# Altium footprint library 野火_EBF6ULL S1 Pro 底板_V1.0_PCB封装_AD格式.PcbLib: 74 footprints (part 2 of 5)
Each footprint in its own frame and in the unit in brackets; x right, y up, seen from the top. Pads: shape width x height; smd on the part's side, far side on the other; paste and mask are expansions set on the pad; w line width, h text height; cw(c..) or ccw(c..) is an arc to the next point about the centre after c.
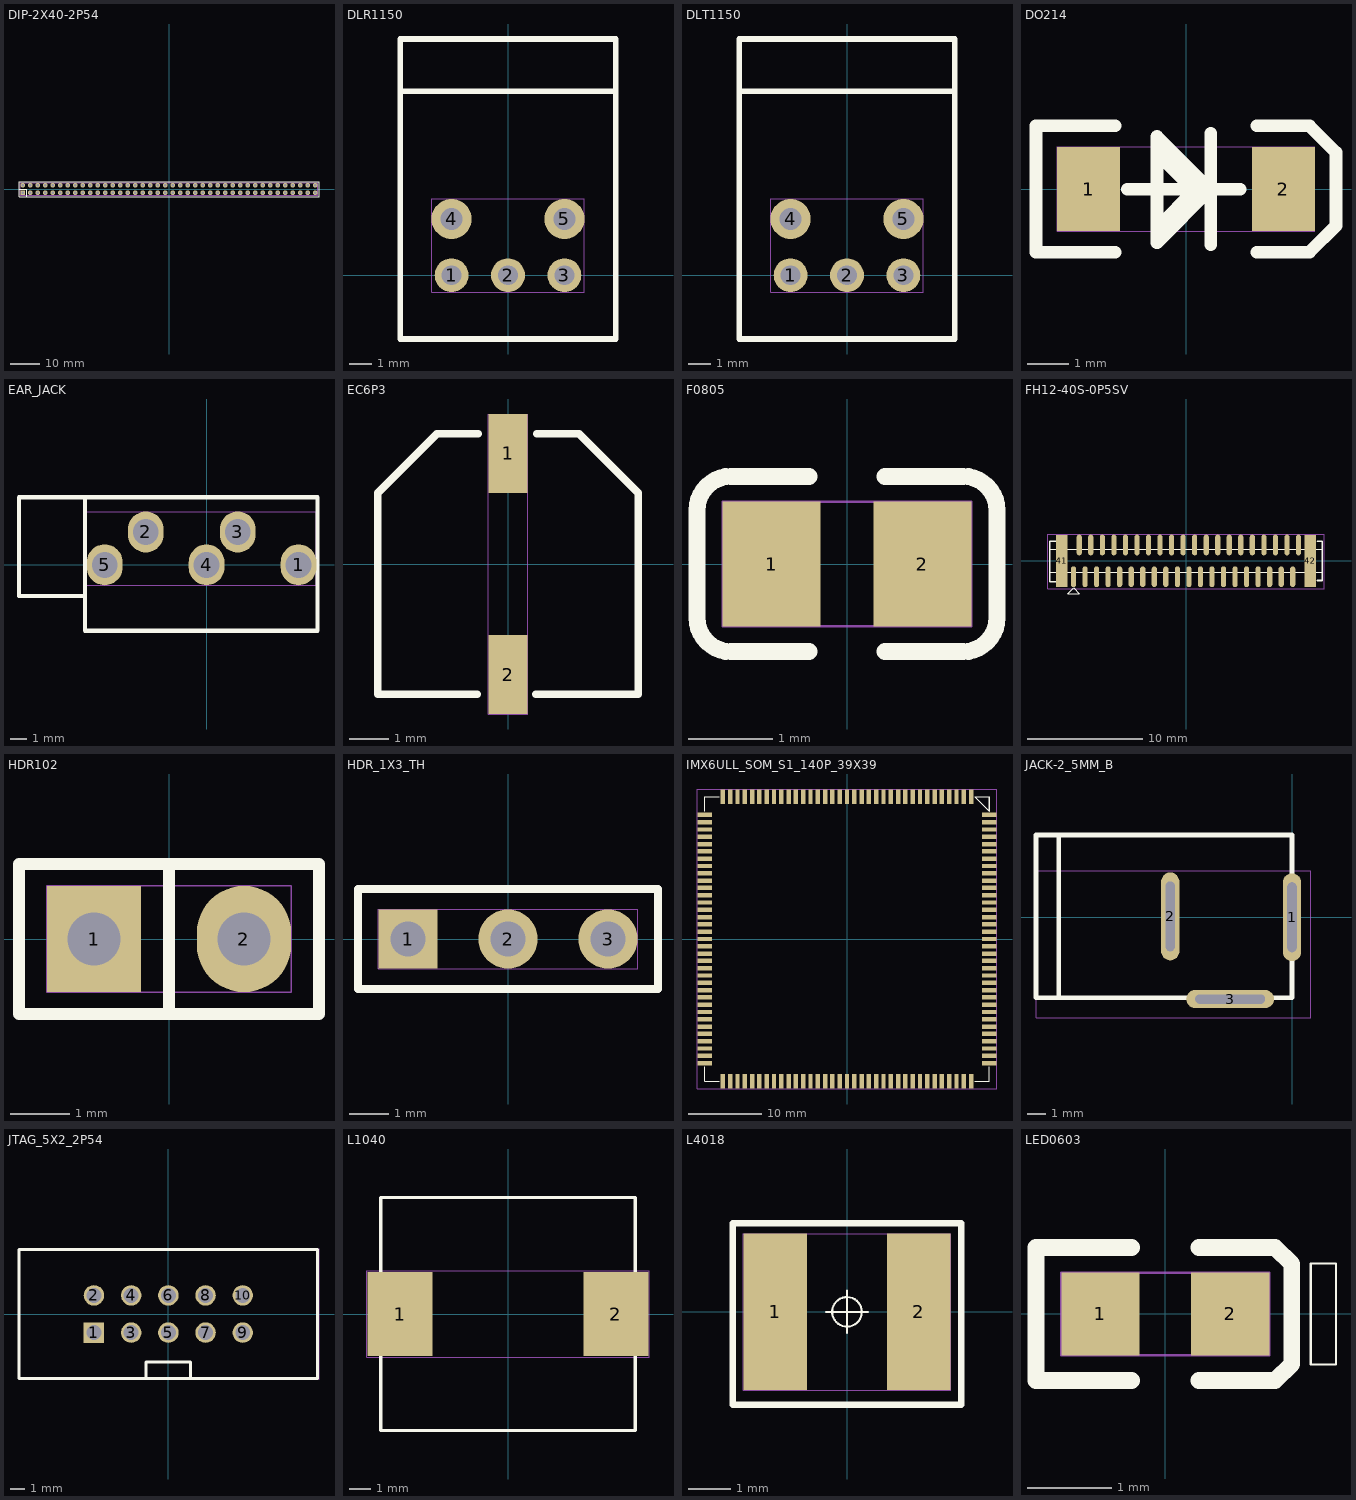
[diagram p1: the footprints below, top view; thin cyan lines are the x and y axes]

## DIP-2X40-2P54 [mil]
pads (80):
  rect 62.99x62.99 hole 35.43 mask+2: 1(-1950,-50)
  round 62.99 hole 35.43 mask+2: 2(-1950,50) 3(-1850,-50) 4(-1850,50) 5(-1750,-50) 6(-1750,50) 7(-1650,-50) 8(-1650,50) 9(-1550,-50) 10(-1550,50) 11(-1450,-50) 12(-1450,50) 13(-1350,-50) 14(-1350,50) 15(-1250,-50) 16(-1250,50) 17(-1150,-50) 18(-1150,50) 19(-1050,-50) 20(-1050,50) 21(-950,-50) 22(-950,50) 23(-850,-50) 24(-850,50) 25(-750,-50) 26(-750,50) 27(-650,-50) 28(-650,50) 29(-550,-50) 30(-550,50) 31(-450,-50) 32(-450,50) 33(-350,-50) 34(-350,50) 35(-250,-50) 36(-250,50) 37(-150,-50) 38(-150,50) 39(-50,-50) 40(-50,50) 41(50,-50) 42(50,50) 43(150,-50) 44(150,50) 45(250,-50) 46(250,50) 47(350,-50) 48(350,50) 49(450,-50) 50(450,50) 51(550,-50) 52(550,50) 53(650,-50) 54(650,50) 55(750,-50) 56(750,50) 57(850,-50) 58(850,50) 59(950,-50) 60(950,50) 61(1050,-50) 62(1050,50) 63(1150,-50) 64(1150,50) 65(1250,-50) 66(1250,50) 67(1350,-50) 68(1350,50) 69(1450,-50) 70(1450,50) 71(1550,-50) 72(1550,50) 73(1650,-50) 74(1650,50) 75(1750,-50) 76(1750,50) 77(1850,-50) 78(1850,50) 79(1950,-50) 80(1950,50)
Top Overlay:
  lines w12: -2000,0 -1900,0 -1900,-100 ; -2000,-100 2000,-100 2000,100 -2000,100 -2000,-100
Top Assembly:
  text "CN5" at 65.11,25 h50
Mechanical 20:
  lines w1: -1981,-81 -1981,81 1981,81 1981,-81 -1981,-81

## DLR1150 [mil]
pads (5):
  round 60 hole 35 mask+2: 1(-100,0) 2(0,0) 3(100,0)
  round 70.87 hole 39.37 mask+2: 4(-100,99.61) 5(100,99.61)
Top Overlay:
  lines w10: -190.94,325.98 190.94,325.98 ; -190.94,325.98 -190.94,-112.99 190.94,-112.99 190.94,325.98 ; -190.94,325.98 -190.94,418.5 190.94,418.5 190.94,325.98
Top Assembly:
  text "CN8" at -65.11,-25 h50
Mechanical 20:
  lines w1: -135.43,-30 135.43,-30 135.43,135.04 -135.43,135.04 -135.43,-30

## DLT1150 [mil]
pads (5):
  round 60 hole 35 mask+2: 1(-100,0) 2(0,0) 3(100,0)
  round 70.87 hole 39.37 mask+2: 4(-100,99.61) 5(100,99.61)
Top Overlay:
  lines w10: -190.94,325.98 -190.94,418.5 190.94,418.5 190.94,325.98 ; -190.94,325.98 -190.94,-112.99 190.94,-112.99 190.94,325.98 ; -190.94,325.98 190.94,325.98
Top Assembly:
  text "CN12" at -83.44,-25 h50
Mechanical 20:
  lines w1: -135.43,-30 135.43,-30 135.43,135.04 -135.43,135.04 -135.43,-30

## DO214 [mil]
pads (2):
  rect 60x80 smd mask+2: 1(-92.5,0) 2(92.5,0)
Top Overlay:
  lines w1: -27.58,-25.06 -27.58,22.87 -1.5,22.87 -1.5,-25.06 -27.58,-25.06
  lines w12: -67.5,-60 -142.5,-60 -142.5,60 -67.5,60 ; -55.58,-0.13 51.42,-0.13 ; -27.58,33.87 7.79,-1.51 -25.84,-35.13 ; 23.42,-53.13 23.42,52.87 ; 67.5,-60 117.42,-60 142.5,-34.92 142.5,34.87 117.37,60 67.5,60 ; -27.58,-51.13 23.42,-0.13 23.42,-1.13 -27.58,49.87 -27.58,-51.13
Top Assembly:
  text "D2" at 38.93,25 h50
Mechanical 20:
  lines w1: -122.5,-40 122.5,-40 122.5,40 -122.5,40 -122.5,-40

## EAR_JACK [mil]
pads (5):
  oval 86x98 hole 62 mask+2: 1(220.47,0) 2(-145.67,78.74) 3(74.8,78.74) 4(0,0) 5(-244.1,0)
Top Overlay:
  lines w10: -294.49,-75.03 -449.49,-75.03 -449.49,161.97 -294.49,161.97 ; -291.49,-158.03 -291.49,161.97 265.51,161.97 265.51,-158.03 -291.49,-158.03
Top Assembly:
  text "J32" at 57.25,25 h50
Mechanical 20:
  lines w1: -287.1,-49 263.47,-49 263.47,127.74 -287.1,127.74 -287.1,-49

## EC6P3 [mm]
pads (2):
  rect 1x2 smd mask+0.051: 1(0,2.8) 2(0,-2.8)
Top Overlay:
  lines w0.2: -0.787,-3.3 -3.3,-3.3 -3.3,1.8 -1.8,3.3 -0.762,3.3 ; 0.711,-3.3 3.3,-3.3 3.3,1.8 1.8,3.3 0.737,3.3
Top Assembly:
  text "C93" at -1.621,-0.635 h1.27
Mechanical 20:
  lines w0.025: -0.5,-3.8 0.5,-3.8 0.5,3.8 -0.5,3.8 -0.5,-3.8

## F0805 [mm]
pads (2):
  rect 1.16x1.47 smd mask+0.051: 1(-0.89,0) 2(0.89,0)
Top Overlay:
  lines w0.2: -0.45,-1.035 -1.37,-1.035 cw(c-1.37,-0.635) -1.77,-0.635 -1.77,0.635 cw(c-1.37,0.635) -1.37,1.035 -0.45,1.035 ; 0.45,-1.035 1.37,-1.035 ccw(c1.37,-0.635) 1.77,-0.635 1.77,0.635 ccw(c1.37,0.635) 1.37,1.035 0.45,1.035
Top Assembly:
  text "F1" at -0.617,-0.635 h1.27
Mechanical 20:
  lines w0.025: -1.47,-0.735 1.47,-0.735 1.47,0.735 -1.47,0.735 -1.47,-0.735

## FH12-40S-0P5SV [mil]
height 196
pads (42):
  oval 17.72x70.87 smd mask+1.97: 1(-383.85,-54.13) 2(-364.17,54.13) 3(-344.48,-54.13) 4(-324.8,54.13) 5(-305.11,-54.13) 6(-285.43,54.13) 7(-265.74,-54.13) 8(-246.06,54.13) 9(-226.37,-54.13) 10(-206.69,54.13) 11(-187,-54.13) 12(-167.32,54.13) 13(-147.63,-54.13) 14(-127.96,54.13) 15(-108.26,-54.13) 16(-88.59,54.13) 17(-68.89,-54.13) 18(-49.22,54.13) 19(-29.52,-54.13) 20(-9.85,54.13) 21(9.85,-54.13) 22(29.52,54.13) 23(49.22,-54.13) 24(68.89,54.13) 25(88.59,-54.13) 26(108.26,54.13) 27(127.96,-54.13) 28(147.63,54.13) 29(167.33,-54.13) 30(187,54.13) 31(206.7,-54.13) 32(226.37,54.13) 33(246.07,-54.13) 34(265.74,54.13) 35(285.44,-54.13) 36(305.11,54.13) 37(324.81,-54.13) 38(344.48,54.13) 39(364.17,-54.13) 40(383.85,54.13)
  rect 39.37x177.17 smd mask+1.97: 41(-423.24,0) 42(423.24,0)
Top Overlay:
  lines w1: -464.56,-39.37 -464.56,39.37 464.56,39.37 464.56,-39.37 -464.56,-39.37 ; -403.7,-111.81 -383.7,-91.81 -363.7,-111.81 -403.7,-111.81
  lines w6: -444.89,-70.87 -464.56,-70.87 -464.56,66.93 -444.89,66.93 ; 448.81,-66.93 464.56,-66.93 464.56,66.93 448.81,66.93
Top Assembly:
  text "J16" at 52.14,25 h50
Mechanical 20:
  lines w1: -472.44,-94.49 -472.44,90.55 472.44,90.55 472.44,-94.49 -472.44,-94.49

## HDR102 [mil]
pads (2):
  rect 62.99x70.87 / inner oval 62.99x70.87 / far side rect 62.99x70.87 hole 35.43 mask+1.97: 1(-50,0)
  oval 62.99x70.87 hole 35.43 mask+1.97: 2(50,0)
Top Overlay:
  lines w8: 0,-50 0,50 ; -100,-50 100,-50 100,50 -100,50 -100,-50
Top Assembly:
  text "J30" at -57.25,-25 h50
Mechanical 20:
  lines w1: -81.5,-35.43 81.5,-35.43 81.5,35.43 -81.5,35.43 -81.5,-35.43

## HDR_1X3_TH [mil]
height 47
pads (3):
  rect 59.06x59.06 hole 35.43 mask+2: 1(-100,0)
  round 59.06 hole 35.43 mask+2: 2(0,0) 3(100,0)
Top Overlay:
  lines w7.87: -150,-50 150,-50 150,50 -150,50 -150,-50
Top Assembly:
  text "J37" at -57.25,-25 h50
Mechanical 20:
  lines w1: -129.53,-29.53 129.53,-29.53 129.53,29.53 -129.53,29.53 -129.53,-29.53

## IMX6ULL_SOM_S1_140P_39X39 [mm]
pads (140):
  rect 0.6x2 smd mask+0.05: 1(17,19.5) 2(16,19.5) 3(15,19.5) 4(14,19.5) 5(13,19.5) 6(12,19.5) 7(11,19.5) 8(10,19.5) 9(9,19.5) 10(8,19.5) 11(7,19.5) 12(6,19.5) 13(5,19.5) 14(4,19.5) 15(3,19.5) 16(2,19.5) 17(1,19.5) 18(0,19.5) 19(-1,19.5) 20(-2,19.5) 21(-3,19.5) 22(-4,19.5) 23(-5,19.5) 24(-6,19.5) 25(-7,19.5) 26(-8,19.5) 27(-9,19.5) 28(-10,19.5) 29(-11,19.5) 30(-12,19.5) 31(-13,19.5) 32(-14,19.5) 33(-15,19.5) 34(-16,19.5) 35(-17,19.5) 71(-17,-19.5) 72(-16,-19.5) 73(-15,-19.5) 74(-14,-19.5) 75(-13,-19.5) 76(-12,-19.5) 77(-11,-19.5) 78(-10,-19.5) 79(-9,-19.5) 80(-8,-19.5) 81(-7,-19.5) 82(-6,-19.5) 83(-5,-19.5) 84(-4,-19.5) 85(-3,-19.5) 86(-2,-19.5) 87(-1,-19.5) 88(0,-19.5) 89(1,-19.5) 90(2,-19.5) 91(3,-19.5) 92(4,-19.5) 93(5,-19.5) 94(6,-19.5) 95(7,-19.5) 96(8,-19.5) 97(9,-19.5) 98(10,-19.5) 99(11,-19.5) 100(12,-19.5) 101(13,-19.5) 102(14,-19.5) 103(15,-19.5) 104(16,-19.5) 105(17,-19.5)
  rect 2x0.6 smd mask+0.05: 36(-19.5,17) 37(-19.5,16) 38(-19.5,15) 39(-19.5,14) 40(-19.5,13) 41(-19.5,12) 42(-19.5,11) 43(-19.5,10) 44(-19.5,9) 45(-19.5,8) 46(-19.5,7) 47(-19.5,6) 48(-19.5,5) 49(-19.5,4) 50(-19.5,3) 51(-19.5,2) 52(-19.5,1) 53(-19.5,0) 54(-19.5,-1) 55(-19.5,-2) 56(-19.5,-3) 57(-19.5,-4) 58(-19.5,-5) 59(-19.5,-6) 60(-19.5,-7) 61(-19.5,-8) 62(-19.5,-9) 63(-19.5,-10) 64(-19.5,-11) 65(-19.5,-12) 66(-19.5,-13) 67(-19.5,-14) 68(-19.5,-15) 69(-19.5,-16) 70(-19.5,-17) 106(19.5,-17) 107(19.5,-16) 108(19.5,-15) 109(19.5,-14) 110(19.5,-13) 111(19.5,-12) 112(19.5,-11) 113(19.5,-10) 114(19.5,-9) 115(19.5,-8) 116(19.5,-7) 117(19.5,-6) 118(19.5,-5) 119(19.5,-4) 120(19.5,-3) 121(19.5,-2) 122(19.5,-1) 123(19.5,0) 124(19.5,1) 125(19.5,2) 126(19.5,3) 127(19.5,4) 128(19.5,5) 129(19.5,6) 130(19.5,7) 131(19.5,8) 132(19.5,9) 133(19.5,10) 134(19.5,11) 135(19.5,12) 136(19.5,13) 137(19.5,14) 138(19.5,15) 139(19.5,16) 140(19.5,17)
Top Overlay:
  lines w0.025: 17.495,19.499 19.5,19.5 19.501,17.495 17.495,19.499
  lines w0.152: -19.5,-19.5 -17.5,-19.5 -19.5,-19.5 ; -19.5,-19.5 -19.5,-17.5 -19.5,-19.5 ; -19.5,19.5 -19.5,17.5 -19.5,19.5 ; -19.5,19.5 -17.5,19.5 -19.5,19.5 ; 19.5,-19.5 17.5,-19.5 19.5,-19.5 ; 19.5,-19.5 19.5,-17.5 19.5,-19.5 ; 19.5,19.5 19.5,17.5 19.5,19.5 ; 19.5,19.5 17.5,19.5 19.5,19.5
Top Assembly:
  text "J12" at -1.355,-0.635 h1.27
Mechanical 20:
  lines w0.025: -20.55,-20.55 20.55,-20.55 20.55,20.55 -20.55,20.55 -20.55,-20.55

## JACK-2_5MM_B [mm]
pads (3):
  oval 1x4.81 / inner oval 1x4.81 / far side oval 2x4.81 hole 0.5 slot 3.81 at 90 deg mask+0.05: 1(0,0) 2(-6.659,0.046)
  oval 4.81x1 / inner oval 4.81x1 / far side oval 4.81x2 hole 0.5 slot 3.81 at 0 deg mask+0.05: 3(-3.383,-4.475)
Top Overlay:
  lines w0.254: -12.755,-4.348 -12.755,4.501 ; -14,-4.399 -14,4.501 0,4.501 0,-4.399 -14,-4.399
Top Assembly:
  text "JACK1" at -2.446,-0.635 h1.27
Mechanical 20:
  lines w0.025: -14,-5.491 1.016,-5.491 1.016,2.535 -14,2.535 -14,-5.491

## JTAG_5X2_2P54 [mil]
pads (10):
  rect 55x55 / inner round 55 / far side rect 55x55 hole 40 mask+2.5: 1(-200,-50)
  round 55 hole 40 mask+2.5: 2(-200,50) 3(-100,-50) 4(-100,50) 5(0,-50) 6(0,50) 7(100,-50) 8(100,50) 9(200,-50) 10(200,50)
Top Overlay:
  lines w8: -60,-170 -60,-130 ; -60,-129.37 60,-129.37 ; 60,-170 60,-130 ; -401.57,-173 401.57,-173 401.57,173 -401.57,173 -401.57,-173
Top Assembly:
  text "J1" at -24.29,-25 h50
Mechanical 20:
  lines w1: -400,-175 405,-175 405,175 -400,175 -400,-175

## L1040 [mm]
height 5.283
pads (2):
  rect 3x3.9 smd mask+0.05: 1(-5,0) 2(5,0)
Top Overlay:
  lines w0.152: -5.9,-5.4 5.9,-5.4 5.9,5.4 -5.9,5.4 -5.9,-5.4
Top Assembly:
  text "L1" at 0.584,0.635 h1.27
Mechanical 20:
  lines w0.025: -6.55,-2 6.55,-2 6.55,2 -6.55,2 -6.55,-2

## L4018 [mm]
height 5.283
pads (2):
  rect 1.5x3.7 smd mask+0.05: 1(-1.7,0) 2(1.7,0)
Top Overlay:
  circle w0.05: c0,0 r0.35
  lines w0.05: -0.5,0 0.5,0 ; 0,-0.5 0,0.5
  lines w0.152: -2.7,-2.2 2.7,-2.2 2.7,2.1 -2.7,2.1 -2.7,-2.2
Top Assembly:
  text "L2" at -0.856,-0.635 h1.27
Mechanical 20:
  lines w0.025: -2.45,-1.85 2.45,-1.85 2.45,1.85 -2.45,1.85 -2.45,-1.85

## LED0603 [mil]
pads (2):
  rect 36.61x38.58 smd mask+1.97: 1(-30.31,0) 2(30.32,0)
Top Overlay:
  lines w1: 67.91,-23.62 67.91,23.62 79.73,23.62 79.73,-23.62 67.91,-23.62
  lines w7.87: -15.75,-31.1 -60.43,-31.1 -60.43,31.1 -15.75,31.1 ; 15.75,-31.1 51.18,-31.1 59.06,-23.5 59.06,23.5 51.18,31.1 15.75,31.1
Top Assembly:
  text "D7" at 38.93,25 h50
Mechanical 20:
  lines w1: -48.62,-19.29 48.62,-19.29 48.62,19.29 -48.62,19.29 -48.62,-19.29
